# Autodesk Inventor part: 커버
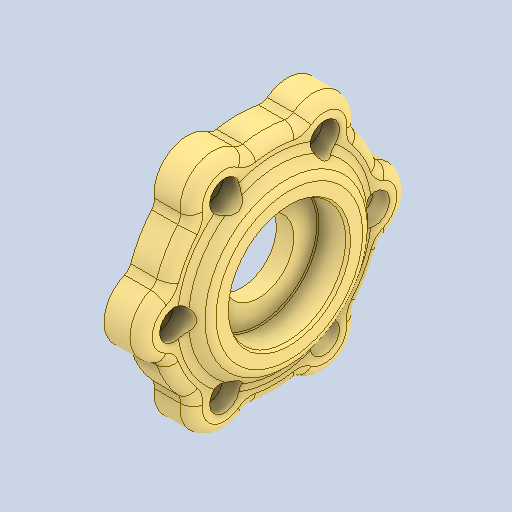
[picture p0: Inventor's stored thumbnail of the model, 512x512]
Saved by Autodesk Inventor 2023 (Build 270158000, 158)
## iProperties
Created: 2026-04
Part Number: 커버
Material: 알루미늄 6061
Document SubType Name: Modeling
Designer: home
Density: 2.7 g/cm^3
Appearance: 기본값
Author: jhkim
Sending System: Autodesk Inventor 2027
Preprocessor: ST-DEVELOPER v20.1
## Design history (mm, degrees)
feature "솔리드1"
node "솔리드2"
